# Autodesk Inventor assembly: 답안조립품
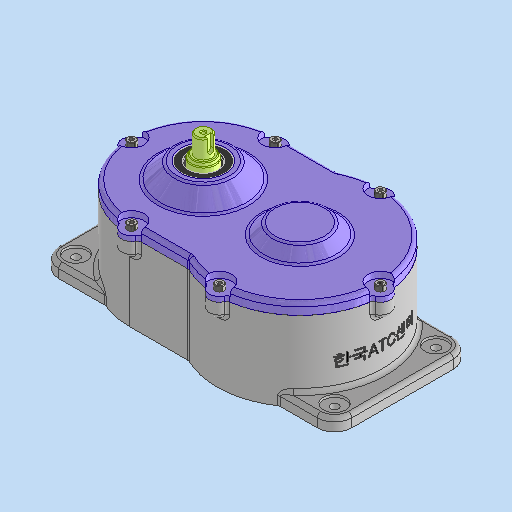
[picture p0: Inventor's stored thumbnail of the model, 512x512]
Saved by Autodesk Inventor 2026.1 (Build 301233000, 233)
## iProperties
Created: 2025-11
Part Number: 답안조립품
Document SubType Name: Assembly
Designer: PC-30
Author: PC-30
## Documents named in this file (19)
- C:\Users\PC-30\Downloads\PDF_20250920_2\답안조립품.iam
- C:\Users\PC-30\Downloads\PDF_20250920_2\본체.ipt
- C:\Users\PC-30\Downloads\PDF_20250920_2\스러스트 볼 베어링 51102.ipt
- C:\Users\PC-30\Downloads\PDF_20250920_2\깊은 홈 볼 베어링 6904.ipt
- C:\Users\PC-30\Downloads\PDF_20250920_2\오일 실 20 35 8.ipt
- C:\Users\PC-30\Downloads\PDF_20250920_2\슬롯 축.ipt
- C:\Users\PC-30\Downloads\PDF_20250920_2\평행 키 6x6x14.ipt
- C:\Users\PC-30\Downloads\PDF_20250920_2\슬롯.ipt
- C:\Users\PC-30\Downloads\PDF_20250920_2\칼라.ipt
- C:\Users\PC-30\Downloads\PDF_20250920_2\구동 축.ipt
- C:\Users\PC-30\Downloads\PDF_20250920_2\구동 휠.ipt
- C:\Users\PC-30\Downloads\PDF_20250920_2\어댑터.ipt
- C:\Users\PC-30\Downloads\PDF_20250920_2\6각 구멍붙이 볼트 M6x12.ipt
- C:\Users\PC-30\Downloads\PDF_20250920_2\커버.ipt
- C:\Users\PC-30\Downloads\PDF_20250920_2\캠 플로워.ipt
- C:\Users\PC-30\Downloads\PDF_20250920_2\평 와셔 M3.ipt
- C:\Users\PC-30\Downloads\PDF_20250920_2\스프링 와셔 M3.ipt
- C:\Users\PC-30\Downloads\PDF_20250920_2\육각 너트 M3.ipt
- C:\Users\PC-30\Downloads\PDF_20250920_2\6각 구멍붙이 볼트 M4x10.ipt
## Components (9 placed, 4 different names)
1. 구동 축:1
2. 구동 휠:1
3. 6각 구멍붙이 볼트 M6x12:1
4. 6각 구멍붙이 볼트 M4x10:1
5. 6각 구멍붙이 볼트 M4x10:3
6. 6각 구멍붙이 볼트 M4x10:4
7. 6각 구멍붙이 볼트 M4x10:2
8. 6각 구멍붙이 볼트 M4x10:5
9. 6각 구멍붙이 볼트 M4x10:6
